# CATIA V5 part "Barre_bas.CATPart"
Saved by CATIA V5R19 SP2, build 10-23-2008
Part number: Barre_bas
Bounding box of the stored display mesh (mm): x -50 to 50, y -779.963 to -284.182, z -149.891 to -38.182
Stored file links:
  G:\EU_thinkMotion\CFAO_2010\MMS_groupe3\MMS_groupe3\pmayet\pmayet_assemblage_animation\pmayet_assemblage_animation\Barre_bas.CATPart
  G:\EU_thinkMotion\CFAO_2010\MMS_groupe3\MMS_groupe3\pmayet\pmayet_assemblage_animation\pmayet_assemblage_animation\pmayet_assemblage_animation.CATProduct
  G:\EU_thinkMotion\CFAO_2010\MMS_groupe3\MMS_groupe3\pmayet\pmayet_assemblage_animation\pmayet_assemblage_animation\Squelette_barre_bas.CATPart
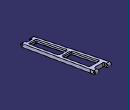
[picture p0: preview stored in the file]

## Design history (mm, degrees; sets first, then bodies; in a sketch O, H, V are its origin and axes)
Parameters
  Rayon_trou = 5 mm
  `Longueur=Angle_Patte_bas +0.9` = 7.9
  Rayon_porte_moyeu = 96 mm
  Distance_entre_rayons(porte_moyeu) = 32 mm
  `épaisseur_barre` = 20 mm
Set1
  Plane1 to Plane3: linked copy from another document
  Point1: linked copy from another document
  Point2: linked copy from another document
  Plane4: linked copy from another document
  Plane5: linked copy from another document
  Point3 to Point5: linked copy from another document
Body1 (main body)
  Sketch1 on Plane1, origin (0, -1.644, 8.5058), H (-1, 0, 0), V (0, 0.9818, 0.1898)
    line L1 (-18.6398, -770.0758) -> (18.6398, -770.0758)
    point P1 (-18.6398, -770.0758)
    point P2 (18.6398, -770.0758)
    reference intersected line E1 through (0, -782.5758) direction (-1, 0) from Plane2
    reference intersected line E2 through (0, -782.5758) direction (-1, 0) from Plane2
    reference intersected line E3 through (0, 0) direction (0, 1) from Plane3
    reference intersected line E4 through (0, 0) direction (0, 1) from Plane3
    line L2 (18.6398, -770.0758) -> (18.6398, -795.0758)
    point P3 (18.6398, -770.0758)
    point P4 (18.6398, -795.0758)
    reference intersected line E5 through (0, 0) direction (0, 1) from Plane3
    line L3 (-18.6398, -770.0758) -> (-18.6398, -795.0758)
    point P5 (-18.6398, -770.0758)
    point P6 (-18.6398, -795.0758)
    reference intersected line E6 through (0, 0) direction (0, 1) from Plane3
    reference intersected line E7 through (0, 0) direction (0, 1) from Plane3
    line L4 (18.6398, -795.0758) -> (38.6398, -795.0758)
    point P7 (18.6398, -795.0758)
    point P8 (38.6398, -795.0758)
    reference intersected line E8 through (0, -782.5758) direction (-1, 0) from Plane2
    reference intersected line E9 through (0, -782.5758) direction (-1, 0) from Plane2
    line L5 (-38.6398, -795.0758) -> (-18.6398, -795.0758)
    point P9 (-38.6398, -795.0758)
    point P10 (-18.6398, -795.0758)
    reference intersected line E10 through (0, -782.5758) direction (-1, 0) from Plane2
    reference intersected line E11 through (0, -782.5758) direction (-1, 0) from Plane2
    line L6 (-24.4444, -553.5046) -> (24.4444, -553.5046)
    point P11 (-24.4444, -553.5046)
    point P12 (24.4444, -553.5046)
    line L7 (-25.0858, -526.8379) -> (25.0858, -526.8379)
    point P13 (-25.0858, -526.8379)
    point P14 (25.0858, -526.8379)
    reference intersected line E12 through (0, -782.5758) direction (-1, 0) from Plane2
    reference intersected line E13 through (0, -782.5758) direction (-1, 0) from Plane2
    reference projected point E14 (0, -540.1712) from Point1
    reference projected point E15 (0, -540.1712) from Point1
    line L8 (-30, -317.7666) -> (30, -317.7666)
    point P15 (-30, -317.7666)
    point P16 (30, -317.7666)
    reference intersected line E16 through (0, -782.5758) direction (-1, 0) from Plane2
    reference projected point E17 (40, -297.7666) from Point2
    reference intersected line E18 through (-40, 0) direction (0, 1) from Plane4
    reference intersected line E19 through (40, 0) direction (0, 1) from Plane5
    point P17 (30, -317.7666)
    line L9 (50, -322.7666) -> (50, -282.7666)
    line L10 (50, -282.7666) -> (30, -282.7666)
    line L11 (30, -282.7666) -> (30, -317.7666)
    point P18 (50, -322.7666)
    reference projected point E20 (40, -297.7666) from Point2
    reference projected point E21 (40, -297.7666) from Point2
    reference projected point E22 (40, -297.7666) from Point2
    line L12 (-50, -282.7666) -> (-30, -282.7666)
    line L13 (-30, -282.7666) -> (-30, -317.7666)
    line L14 (-50, -322.7666) -> (-50, -282.7666)
    point P23 (-30, -317.7666)
    point P24 (-50, -322.7666)
    reference projected point E23 (-40, -297.7666) from Point3
    reference projected point E24 (-40, -297.7666) from Point3
    reference projected point E25 (-40, -297.7666) from Point3
    line L15 (50, -322.7666) -> (38.6398, -795.0758)
    point P25 (50, -322.7666)
    point P26 (38.6398, -795.0758)
    line L16 (-50, -322.7666) -> (-38.6398, -795.0758)
    point P27 (-50, -322.7666)
    point P28 (-38.6398, -795.0758)
    line L17 (-29.3929, -347.7666) -> (29.3929, -347.7666)
    point P29 (-29.3929, -347.7666)
    point P30 (29.3929, -347.7666)
    reference projected point E26 (0, -297.7666) from Point5
    reference intersected line E27 through (0, -782.5758) direction (-1, 0) from Plane2
    line L18 (29.3929, -347.7666) -> (25.0858, -526.8379)
    point P31 (29.3929, -347.7666)
    point P32 (25.0858, -526.8379)
    line L19 (-29.3929, -347.7666) -> (-25.0858, -526.8379)
    point P33 (-29.3929, -347.7666)
    point P34 (-25.0858, -526.8379)
    line L20 (-19.7164, -750.0758) -> (19.7164, -750.0758)
    point P35 (-19.7164, -750.0758)
    point P36 (19.7164, -750.0758)
    reference projected point E28 (0, -782.5758) from Point4
    reference intersected line E29 through (0, -782.5758) direction (-1, 0) from Plane2
    line L21 (24.4444, -553.5046) -> (19.7164, -750.0758)
    point P37 (24.4444, -553.5046)
    point P38 (19.7164, -750.0758)
    line L22 (-24.4444, -553.5046) -> (-19.7164, -750.0758)
    point P39 (-24.4444, -553.5046)
    point P40 (-19.7164, -750.0758)
    distance L1 E1 = 12.5 {= Rayon_trou *2.5}
    distance P1 E3 = 18.6398 {= (Rayon_porte_moyeu + Distance_entre_rayons(porte_moyeu) )*`Longueur=Angle_Patte_bas +0.9` *3.14/180 +1mm}
    distance E4 P2 = 18.6398 {= (Rayon_porte_moyeu + Distance_entre_rayons(porte_moyeu) )*`Longueur=Angle_Patte_bas +0.9` *3.14/180 +1mm}
    distance E5 L2 = 18.6398 {= (Rayon_porte_moyeu + Distance_entre_rayons(porte_moyeu) )*`Longueur=Angle_Patte_bas +0.9` *3.14/180 +1mm}
    distance P3 P2 = 0
    length L2 = 25 {= Rayon_trou *5}
    distance L3 E6 = 18.6398 {= (Rayon_porte_moyeu + Distance_entre_rayons(porte_moyeu) )*`Longueur=Angle_Patte_bas +0.9` *3.14/180 +1mm}
    distance P1 P5 = 0
    length L3 = 25 {= Rayon_trou *5}
    distance E8 L4 = 12.5 {= Rayon_trou *2.5}
    distance P4 P7 = 0
    length L4 = 20 {= `épaisseur_barre`}
    distance E10 L5 = 12.5 {= Rayon_trou *2.5}
    distance P10 P6 = 0
    length L5 = 20 {= `épaisseur_barre`}
    distance E14 L7 = 13.3333 {= `épaisseur_barre` * 2/3}
    distance E15 L6 = 13.3333 {= `épaisseur_barre` *2/3}
    distance E17 L8 = 20 {= `épaisseur_barre`}
    distance E18 P15 = 10 {= `épaisseur_barre` /2}
    distance P16 E19 = 10 {= `épaisseur_barre` /2}
    distance E20 L11 = 10 {= `épaisseur_barre` /2}
    distance P17 P16 = 0
    distance L10 E21 = 15 {= Rayon_trou *3}
    distance E22 L9 = 10 {= `épaisseur_barre` /2}
    length L9 = 40 {= `épaisseur_barre` *2}
    distance E23 L12 = 15 {= Rayon_trou *3}
    distance L13 E24 = 10 {= `épaisseur_barre` /2}
    distance E25 L14 = 10 {= `épaisseur_barre` /2}
    distance P15 P23 = 0
    length L14 = 40 {= `épaisseur_barre` *2}
    distance P27 P24 = 0
    distance P28 P9 = 0
    distance P18 P25 = 0
    distance P26 P8 = 0
    distance P12 L15 = 20 {= `épaisseur_barre`}
    distance L15 P14 = 20 {= `épaisseur_barre`}
    distance P13 L16 = 20 {= `épaisseur_barre`}
    distance L16 P11 = 20 {= `épaisseur_barre`}
    distance E26 L17 = 50 {= `épaisseur_barre` *2.5}
    distance L15 P30 = 20 {= `épaisseur_barre`}
    distance P29 L16 = 20 {= `épaisseur_barre`}
    distance P29 P33 = 0
    distance P13 P34 = 0
    distance P30 P31 = 0
    distance P14 P32 = 0
    distance E28 L20 = 32.5 {= Rayon_trou *2.5 + `épaisseur_barre`}
    distance P35 L16 = 20 {= `épaisseur_barre`}
    distance P36 L15 = 20 {= `épaisseur_barre`}
    distance P37 P12 = 0
    distance P38 P36 = 0
    distance P39 P11 = 0
    distance P40 P35 = 0
    parallelism: L1 E2, L3 E7, E9 L4, E11 L5, E12 L6, E13 L7, E16 L8, L17 E27, E29 L20
    vertical: L2 V, L3 V, L9 V, L11 V, L14 V, L13 V
    horizontal: L10 H, L12 H
    coincidence: P37 L6
  Pad1: profile Sketch1, direction (0, 0.1898, -0.9818), length 10 {= Rayon_trou *2}, mirrored extent
  Fillet1: radius 5, on edge [face of Pad1 from Sketch1.L20 | face of Pad1 from Sketch1.L21]
  Fillet2: radius 5, on edge [face of Pad1 from Sketch1.L22 | face of Pad1 from Sketch1.L20]
  Fillet3: radius 5, on edge [face of Pad1 from Sketch1.L7 | face of Pad1 from Sketch1.L18]
  Fillet4: radius 5, on edge [face of Pad1 from Sketch1.L21 | face of Pad1 from Sketch1.L6]
  Fillet5: radius 5, on edge [face of Pad1 from Sketch1.L6 | face of Pad1 from Sketch1.L22]
  Fillet6: radius 5, on edge [face of Pad1 from Sketch1.L19 | face of Pad1 from Sketch1.L7]
  Fillet7: radius 5, on edge [face of Pad1 from Sketch1.L18 | face of Pad1 from Sketch1.L17]
  Fillet8: radius 5, on edge [face of Pad1 from Sketch1.L17 | face of Pad1 from Sketch1.L19]
  Fillet9: radius 5, on edge [face of Pad1 from Sketch1.L8 | face of Pad1 from Sketch1.L11]
  Fillet10: radius 5, on edge [face of Pad1 from Sketch1.L13 | face of Pad1 from Sketch1.L8]
  Fillet11: radius 4, on edge [face of Pad1 from Sketch1.L2 | face of Pad1 from Sketch1.L1]
  Fillet12: radius 4, on edge [face of Pad1 from Sketch1.L1 | face of Pad1 from Sketch1.L3]
  Fillet13: radius 4, on edge [face of Pad1 from Sketch1.L3 | face of Pad1 from Sketch1.L5]
  Fillet14: radius 4, on edge [face of Pad1 from Sketch1.L4 | face of Pad1 from Sketch1.L2]
  Sketch2 on Plane3, origin (0, 0, 0), H (0, -1, 0), V (0, 0, 1)
    arc A1 centre (294, -48) radius 10 from (295.8977, -38.1817) to (292.1023, -57.8183) ccw
    point P1 (294, -48)
    point P2 (295.8977, -38.1817)
    point P3 (292.1023, -57.8183)
    reference projected point E1 (294, -48) from Point2
    reference projected line E2 (320.4434, -42.9258) -> (271.3519, -33.4376) from edge [start face of Pad1 | face of Pad1 from Sketch1.L9]
    reference projected line E3 (316.6481, -62.5624) -> (267.5566, -53.0742) from edge [face of Pad1 from Sketch1.L9 | end face of Pad1]
    point P4 (292.1023, -57.8183)
    line L1 (292.1023, -57.8183) -> (277.3749, -54.9718)
    line L2 (277.3749, -54.9718) -> (281.1702, -35.3352)
    line L3 (281.1702, -35.3352) -> (295.8977, -38.1817)
    point P7 (295.8977, -38.1817)
    reference projected line E4 (281.1702, -35.3352) -> (277.3749, -54.9718) from edge [face of Pad1 from Sketch1.L10 | face of Pad1 from Sketch1.L9]
    reference projected line E5 (281.1702, -35.3352) -> (277.3749, -54.9718) from edge [face of Pad1 from Sketch1.L10 | face of Pad1 from Sketch1.L9]
    reference projected line E6 (320.4434, -42.9258) -> (271.3519, -33.4376) from edge [start face of Pad1 | face of Pad1 from Sketch1.L9]
    reference projected line E7 (320.4434, -42.9258) -> (271.3519, -33.4376) from edge [start face of Pad1 | face of Pad1 from Sketch1.L9]
    distance P2 E2 = 0
    distance P3 E3 = 0
    radius A1 = 10 {= Rayon_trou *2}
    distance E5 L2 = 0
    distance L3 E7 = 0
    length L2 = 20 {= Rayon_trou *4}
    distance P7 P2 = 0
    distance P4 P3 = 0
    coincidence: P1 E1
    parallelism: E4 L2, L3 L1, L3 E6
  Pocket1: profile Sketch2, direction (1, 0, 0), length 60, mirrored extent
  Sketch3 on Plane3, origin (0, 0, 0), H (0, -1, 0), V (0, 0, 1)
    arc A1 centre (770, -140) radius 10 from (768.1023, -149.8183) to (771.8977, -130.1817) ccw
    point P1 (770, -140)
    point P2 (768.1023, -149.8183)
    point P3 (771.8977, -130.1817)
    reference projected point E1 (770, -140) from Point4
    reference projected line E2 (780.3752, -152.1904) -> (326.4664, -64.4601) from edge [face of Pad1 from Sketch1.L15 | end face of Pad1]
    reference projected line E3 (784.1705, -132.5538) -> (330.2617, -44.8235) from edge [start face of Pad1 | face of Pad1 from Sketch1.L15]
    point P4 (771.8977, -130.1817)
    line L1 (771.8977, -130.1817) -> (784.1705, -132.5538)
    line L2 (784.1705, -132.5538) -> (780.3752, -152.1904)
    line L3 (780.3752, -152.1904) -> (768.1023, -149.8183)
    point P7 (768.1023, -149.8183)
    reference projected line E4 (784.1705, -132.5538) -> (330.2617, -44.8235) from edge [start face of Pad1 | face of Pad1 from Sketch1.L15]
    reference projected line E5 (784.1705, -132.5538) -> (780.3752, -152.1904) from edge [face of Pad1 from Sketch1.L15 | face of Pad1 from Sketch1.L4]
    reference projected line E6 (784.1705, -132.5538) -> (330.2617, -44.8235) from edge [start face of Pad1 | face of Pad1 from Sketch1.L15]
    reference projected line E7 (784.1705, -132.5538) -> (780.3752, -152.1904) from edge [face of Pad1 from Sketch1.L15 | face of Pad1 from Sketch1.L4]
    radius A1 = 10 {= Rayon_trou *2}
    distance P2 E2 = 0
    distance P3 E3 = 0
    distance E6 L1 = 0
    distance E7 L2 = 0
    distance P3 P4 = 0
    distance P2 P7 = 0
    coincidence: E1 P1
    parallelism: L1 L3, E4 L1, L2 E5
  Pocket2: profile Sketch3, direction (1, 0, 0), length 60, mirrored extent
  Fillet15: radius 5, on edge [face of Pad1 from Sketch1.L7 | start face of Pad1]
  Fillet16: radius 5, on edge [face of Pad1 from Sketch1.L21 | start face of Pad1]
  Fillet17: radius 5, on edge [end face of Pad1 | face of Pad1 from Sketch1.L22]
  Fillet18: radius 5, on edge [end face of Pad1 | face of Pad1 from Sketch1.L7]
  Sketch4 on Plane3, origin (0, 0, 0), H (0, -1, 0), V (0, 0, 1)
    circle A1 centre (770, -140) radius 5
    point P1 (770, -140)
    reference projected point E1 (770, -140) from Point4
    distance A1 P1 = 5 {= Rayon_trou}
    coincidence: P1 E1
  Pocket3: profile Sketch4, direction (1, 0, 0), length 60, mirrored extent
  Sketch5 on Plane3, origin (0, 0, 0), H (0, -1, 0), V (0, 0, 1)
    circle A1 centre (294, -48) radius 5
    point P1 (294, -48)
    reference projected point E1 (294, -48) from Point5
    distance P1 A1 = 5 {= Rayon_trou}
    coincidence: P1 E1
  Pocket4: profile Sketch5, direction (1, 0, 0), length 60, mirrored extent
